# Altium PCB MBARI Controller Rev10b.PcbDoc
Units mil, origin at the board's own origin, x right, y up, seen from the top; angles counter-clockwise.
Board outline 10420.2 x 10420.2 mil, 2 copper layers (Top Layer, Bottom Layer); 250 components, 200 nets, 891 pads, 0 vias.
Unrouted connection lines stored in the file: 523.
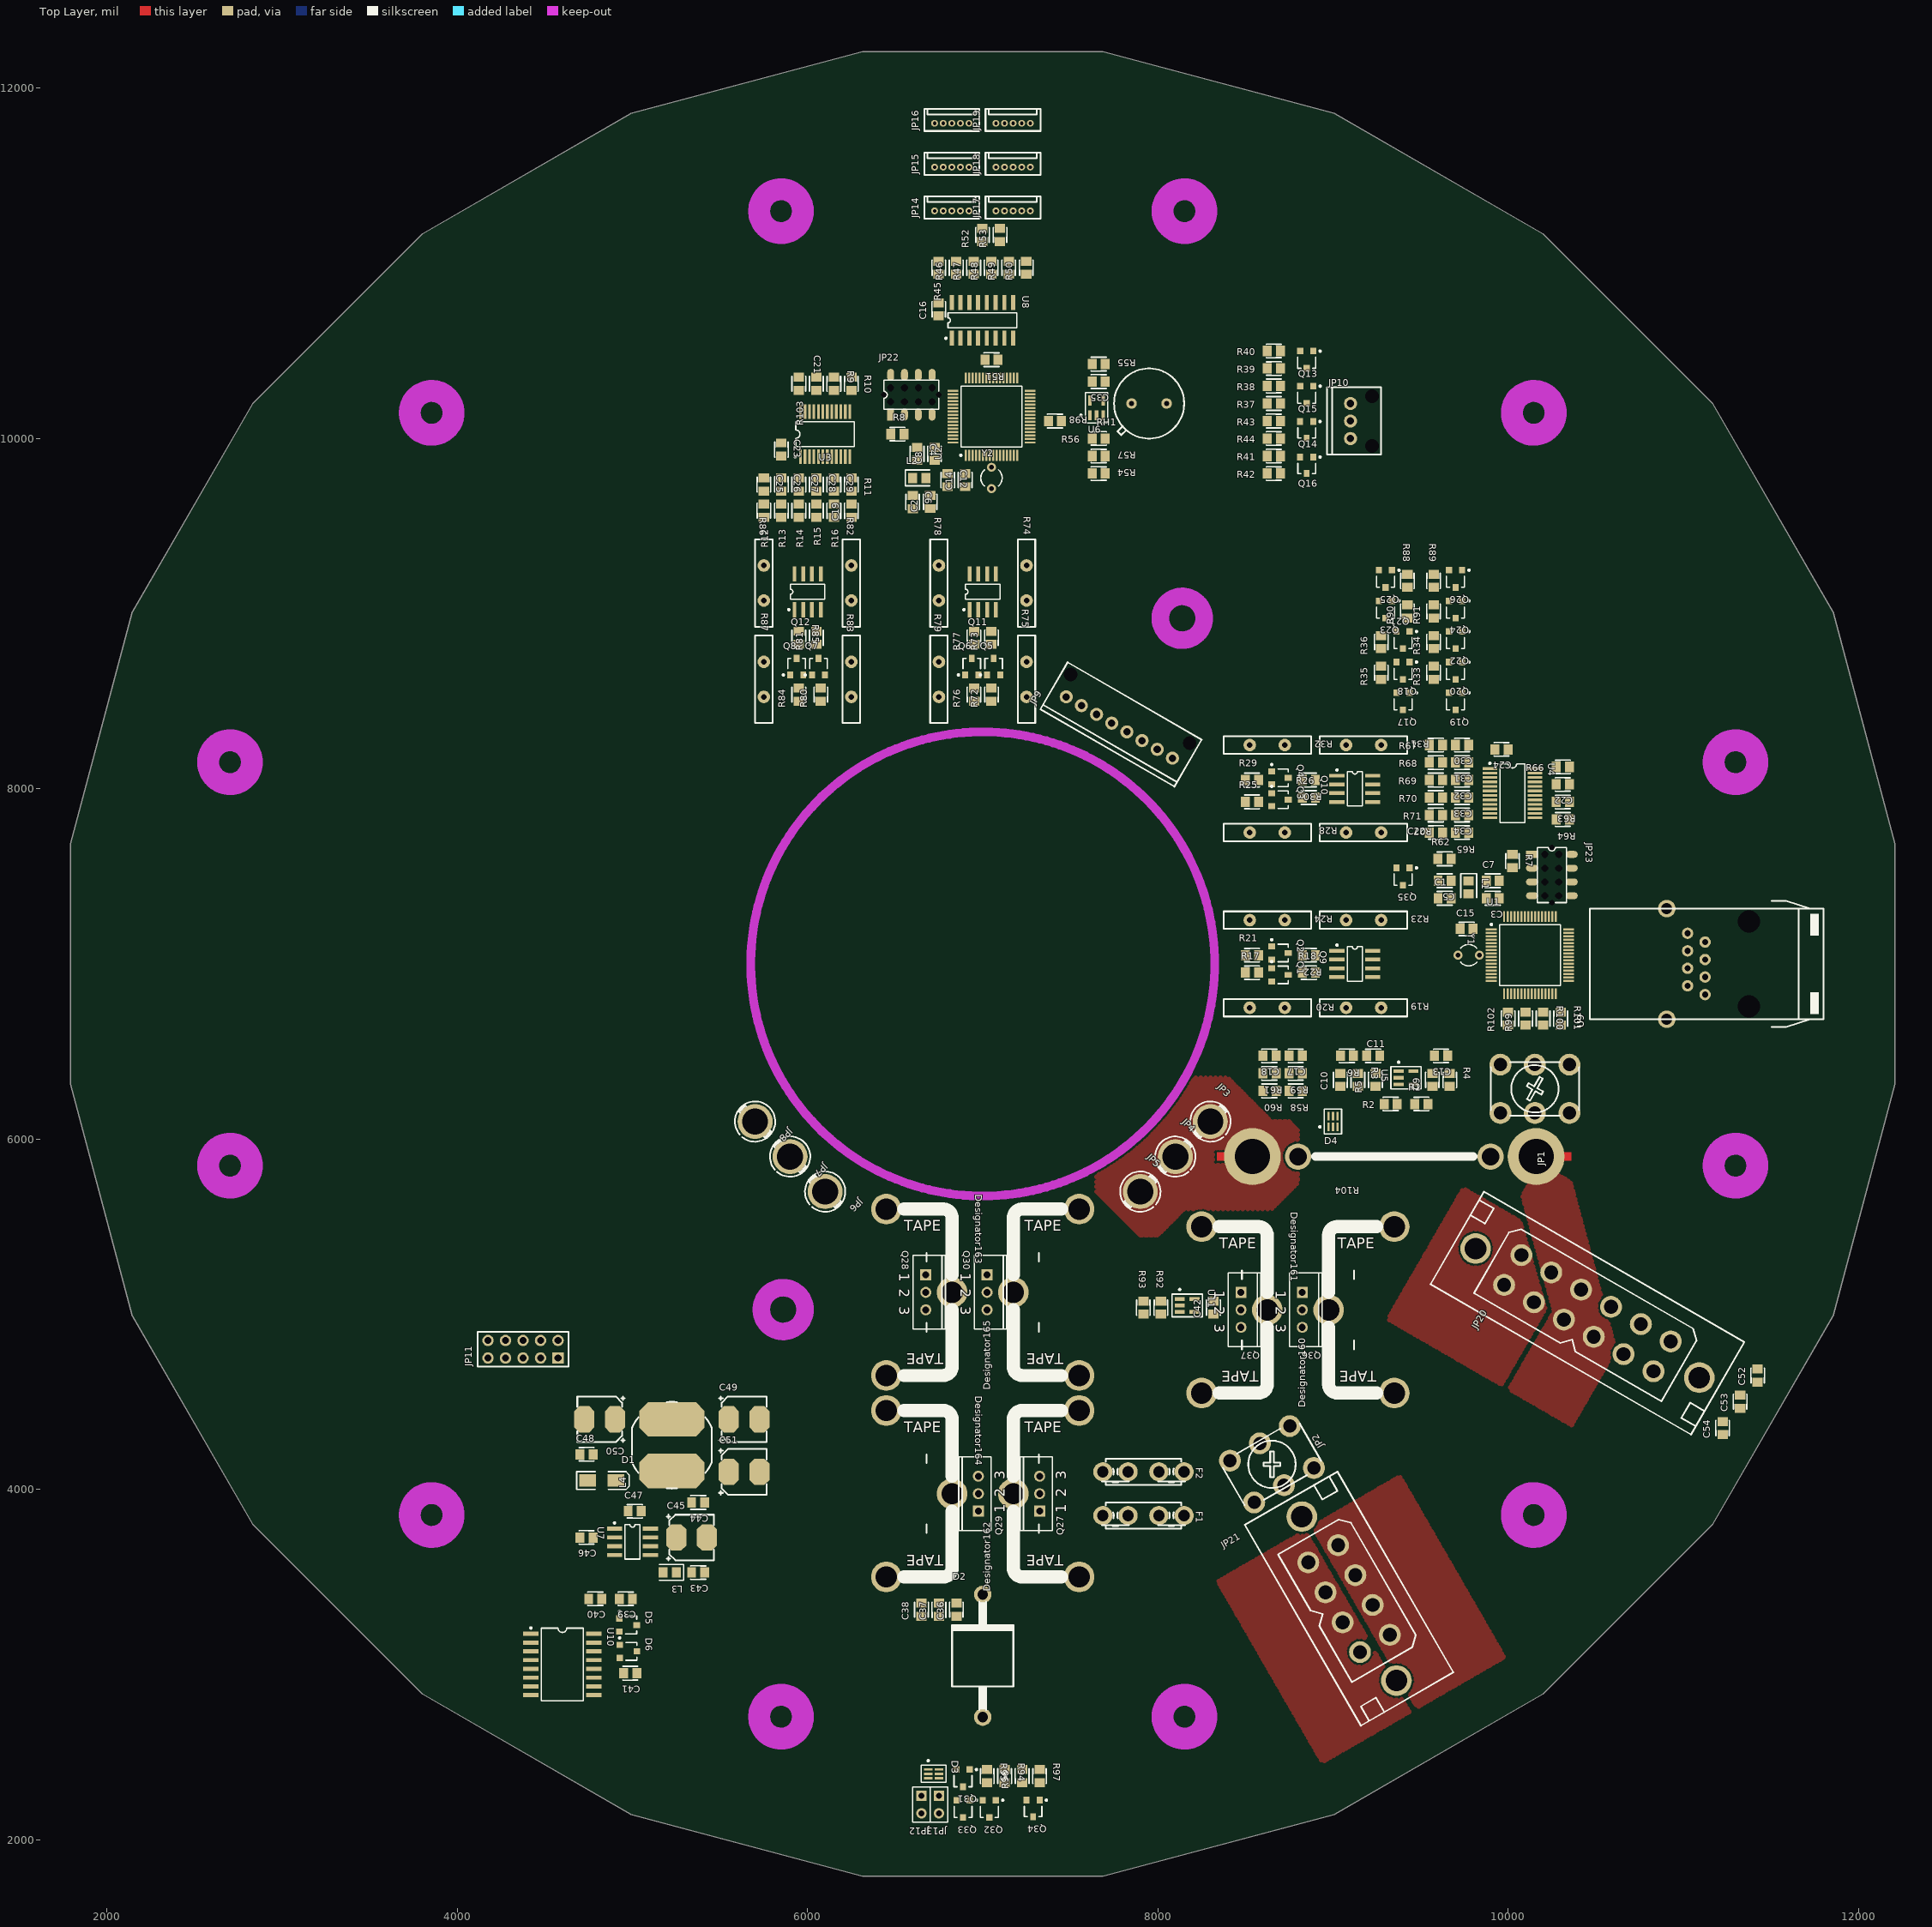
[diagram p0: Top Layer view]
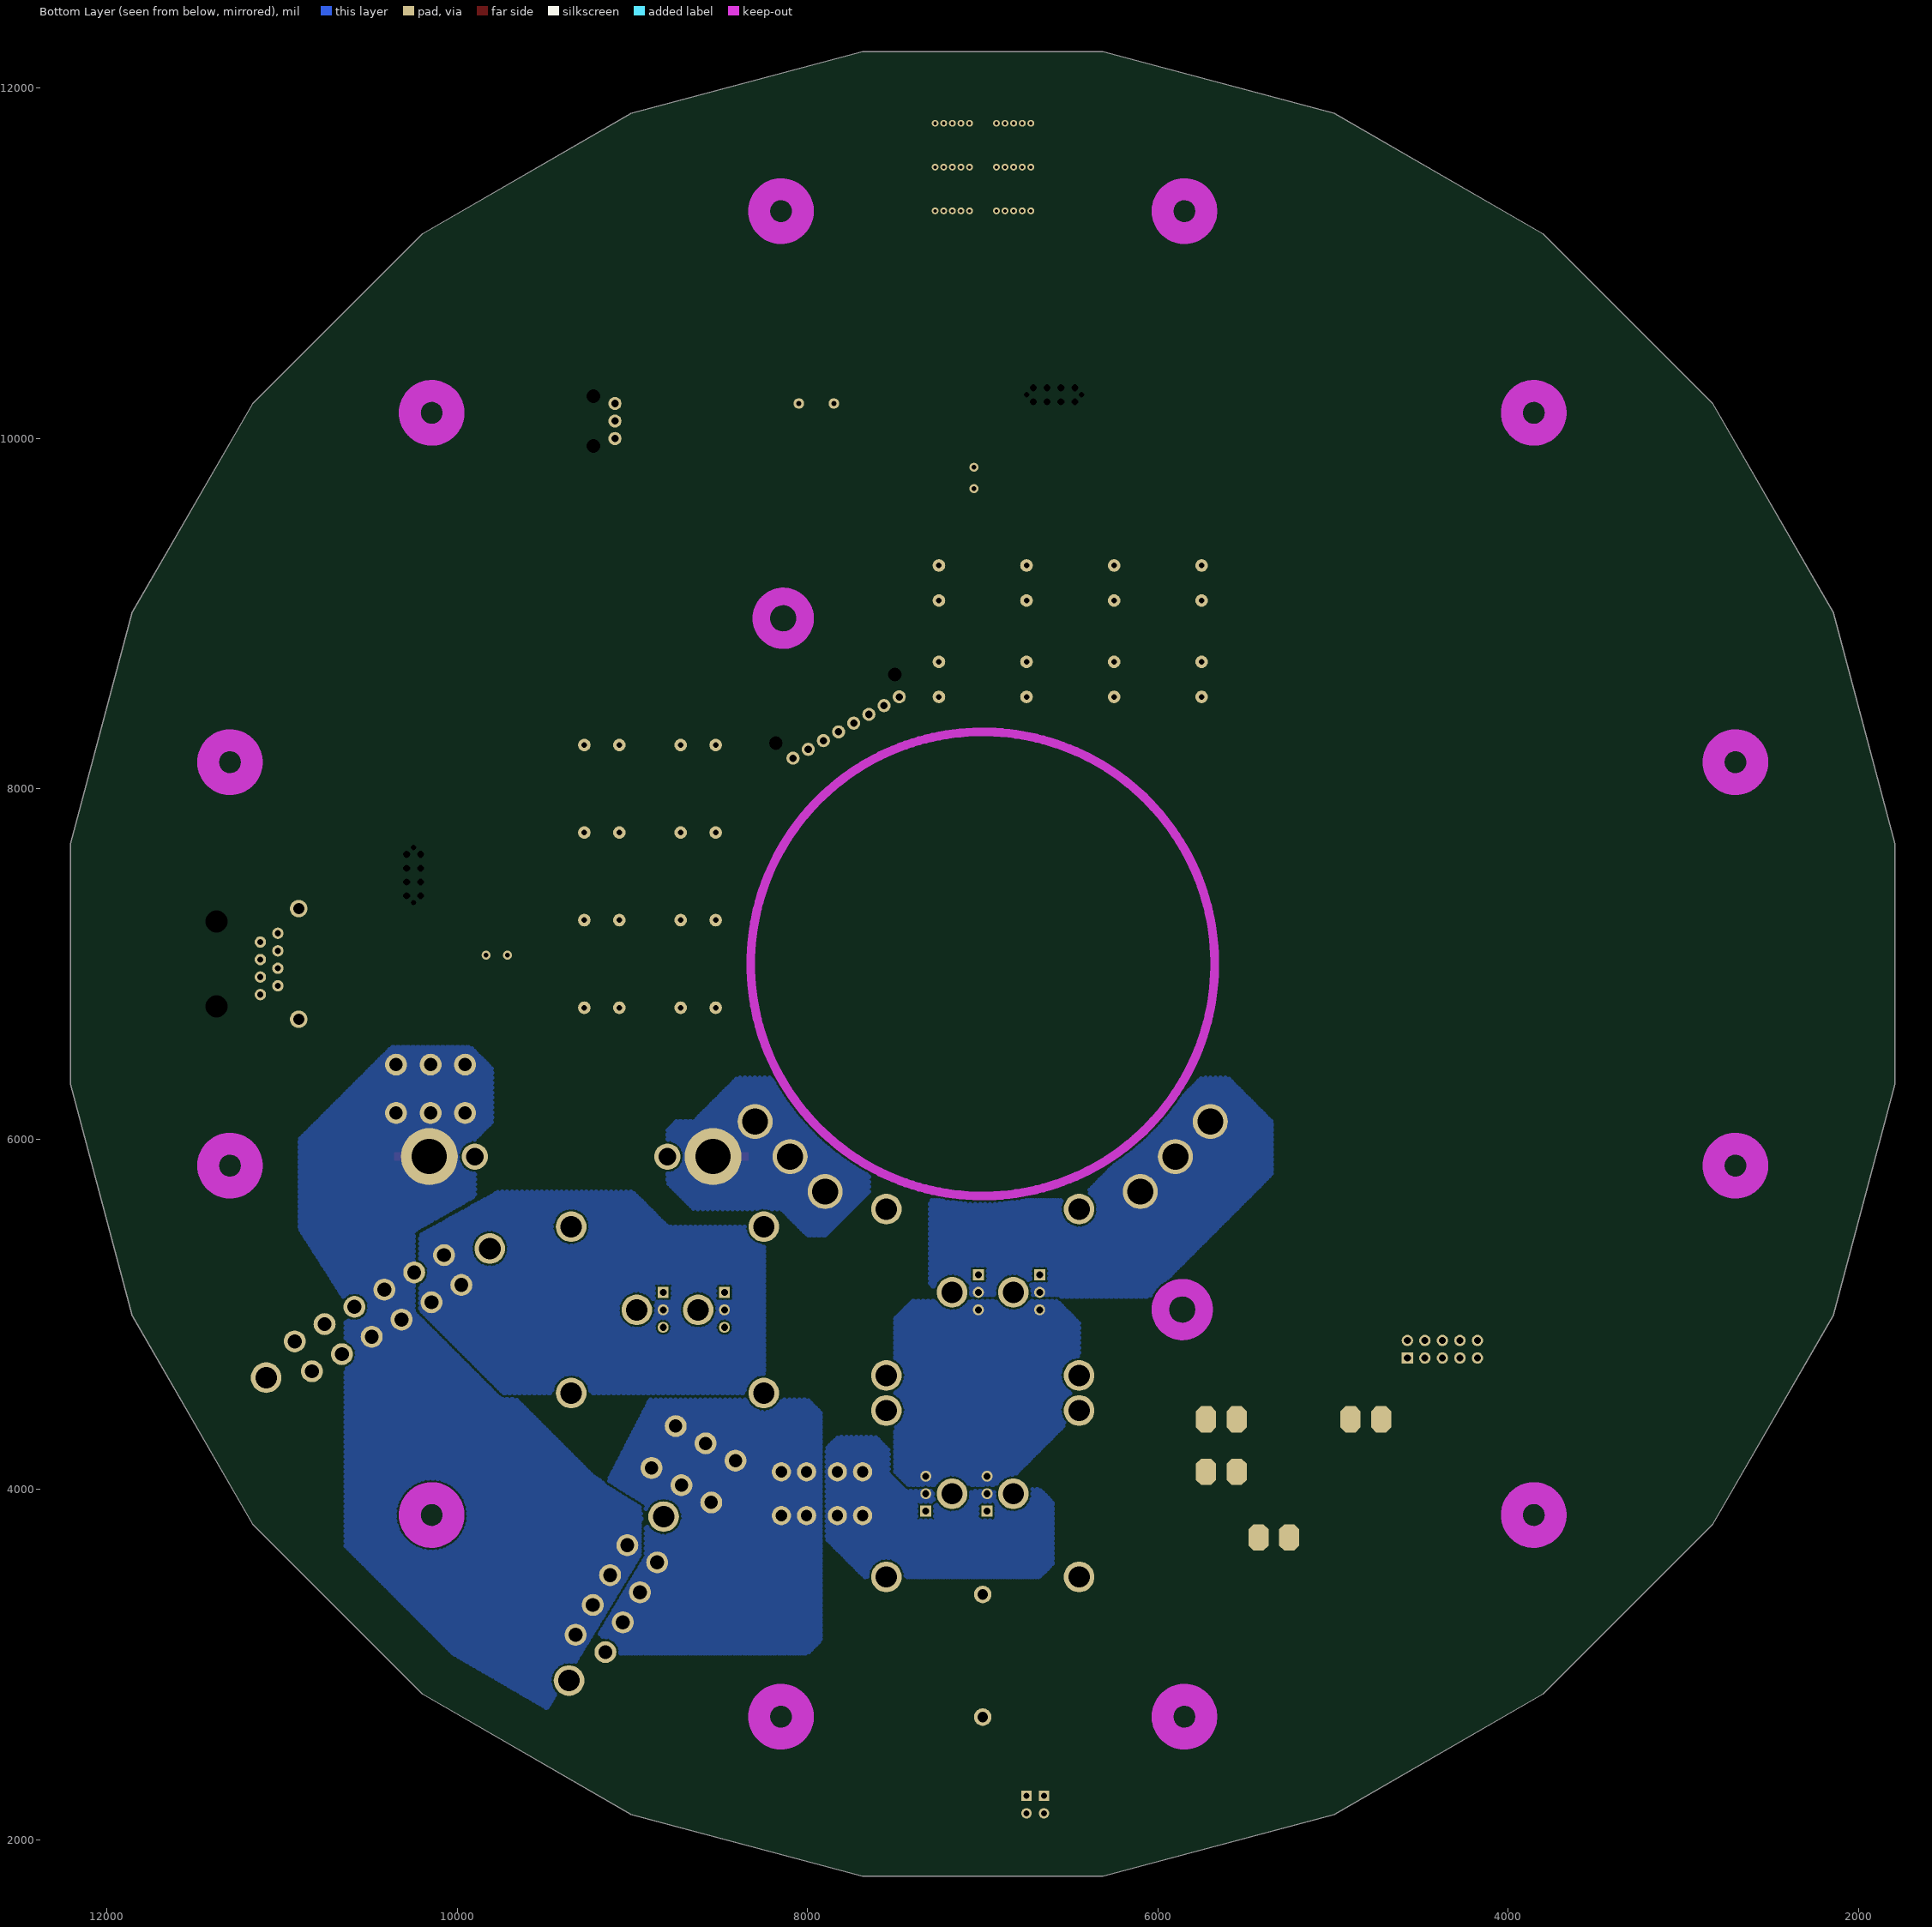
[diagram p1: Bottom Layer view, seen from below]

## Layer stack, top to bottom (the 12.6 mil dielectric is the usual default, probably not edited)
Top Layer: signal copper 1.4
Dielectric: dielectric 12.6, FR-4, Dk 4.8
Bottom Layer: signal copper 1.4

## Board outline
2145.29,4988.4 cw(c2149.63,4990.91) 2144.88,4989.33 cw(c2149.63,4990.91) 2144.79,4989.61 1790.07,6313.44 cw(c1794.91,6314.74) 1789.9,6314.74 ccw(c1794.91,6314.74) 1790.07,6313.44 1789.9,6314.74 1789.9,7685.26 cw(c1794.91,7685.26) 1790.08,7686.58 2144.79,9010.39 cw(c2149.63,9009.09) 2145.3,9011.62 2830.55,10198.5 cw(c2834.9,10196) 2831.35,10199.54 cw(c2834.9,10196) 2831.37,10199.56 2831.35,10199.54 3800.46,11168.65 cw(c3804,11165.1) 3801.52,11169.46 4988.4,11854.71 cw(c4990.91,11850.37) 4989.33,11855.12 cw(c4990.91,11850.37) 4989.61,11855.21 6313.44,12209.93 cw(c6314.74,12205.08) 6314.74,12210.1 ccw(c6314.74,12205.08) 6313.44,12209.93 6314.74,12210.1 7685.26,12210.1 cw(c7685.26,12205.08) 7686.58,12209.92 9010.39,11855.21 cw(c9009.09,11850.37) 9011.62,11854.7 10198.5,11169.45 cw(c10196,11165.1) 10199.54,11168.65 cw(c10196,11165.1) 10199.56,11168.63 10199.54,11168.65 11168.65,10199.54 cw(c11165.1,10196) 11169.46,10198.48 11854.71,9011.6 cw(c11850.37,9009.09) 11855.21,9010.37 11855.21,9010.39 ccw(c11850.37,9009.09) 11854.71,9011.6 11855.21,9010.37 12209.93,7686.56 cw(c12205.08,7685.26) 12210.1,7685.26 ccw(c12205.08,7685.26) 12209.93,7686.56 12210.1,7685.26 12210.1,6314.74 cw(c12205.08,6314.74) 12209.95,6313.52 cw(c12205.08,6314.74) 12209.93,6313.44 12209.93,6313.43 ccw(c12205.08,6314.74) 12209.93,6313.45 12209.93,6313.43 11855.21,4989.61 cw(c11850.37,4990.91) 11854.7,4988.38 11854.71,4988.4 ccw(c11850.37,4990.91) 11855.21,4989.61 11854.7,4988.38 11169.45,3801.5 cw(c11165.1,3804) 11168.65,3800.46 ccw(c11165.1,3804) 11169.45,3801.5 11168.65,3800.46 cw(c11165.1,3804) 11168.63,3800.44 11168.65,3800.46 10199.54,2831.35 cw(c10196,2834.9) 10198.48,2830.54 10198.5,2830.55 ccw(c10196,2834.9) 10199.54,2831.35 10198.48,2830.54 9011.6,2145.29 cw(c9009.09,2149.63) 9010.67,2144.88 ccw(c9009.09,2149.63) 9011.6,2145.29 9010.67,2144.88 cw(c9009.09,2149.63) 9010.39,2144.79 ccw(c9009.09,2149.63) 9010.67,2144.88 9010.39,2144.79 7686.56,1790.07 cw(c7685.26,1794.91) 7685.26,1789.9 ccw(c7685.26,1794.91) 7686.56,1790.07 7685.26,1789.9 6314.74,1789.9 cw(c6314.74,1794.91) 6313.42,1790.08 4989.61,2144.79 cw(c4990.91,2149.63) 4988.38,2145.3 3801.5,2830.55 cw(c3804,2834.9) 3800.46,2831.35 cw(c3804,2834.9) 3800.44,2831.37 3800.46,2831.35 2831.35,3800.46 cw(c2834.9,3804) 2830.54,3801.52

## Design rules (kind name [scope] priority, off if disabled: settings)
Clearance "Clearance - Polygon" [NOT(IsPolygon) vs (IsPolygon)] p1: gap=25
Clearance [NOT(IsPolygon) vs NOT(IsPolygon)] p2: gap=10
ComponentClearance [All] p1: gap=10 collisioncheckmode=0
PlaneClearance [All] p1: clearance=35
PolygonConnect [All] p1: connectstyle=Direct reliefconductorwidth=10 reliefentries=4 polygonreliefangle="90 Angle"
RoomDefinition "MBARI Controller Rev10b" [InComponentClass('MBARI Controller Rev10b')] p1: confinementstyle=ConfineIn formatcopy=TRUE outline 0,0 2000,0 2000,1000 0,1000
RoutingVias [All] p1: holewidth=10 width=25 viastyle="Through Hole" minholewidth=10 minwidth=25 maxholewidth=100 maxwidth=150
SolderMaskExpansion [All] p1: expansion=4
TestPointUsage [All] p1: valid=0 allowmultiple=FALSE
Testpoint [All] p1: side=15 testpointundercomponent=TRUE minsize=40 maxsize=100 preferedsize=60 minholesize=0 maxholesize=40 preferedholesize=32 testpointgrid=1 style=1023 order=-539222988
Width [All] p1: maxlimit=200 minlimit=10 preferedwidth=10
16 further rules are at their usual default settings.

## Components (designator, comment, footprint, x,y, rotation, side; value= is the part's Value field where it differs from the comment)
C1 "C0805" 0805 9637.6,7375 r0 top locked
C2 "C0805" 0805 6700,9637.6 r90 top locked
C3 "C0805" 0805 9912.4,7375 r180 top locked
C4 "C0805" 0805 6625,9912.4 r270 top locked
C5 "C0805" 0805 9637.6,7475 r180 top locked
C6 "C0805" 0805 6600,9637.4 r270 top locked
C7 "C0805" 0805 9912.6,7475 r0 top locked
C8 "C0805" 0805 6725,9912.4 r90 top locked
C9 "C0805" 0805 9567.32,6337.4 r90 top locked
C10 "C0805" 0805 9042.32,6337.4 r90 top locked
C11 "C0805" 0805 9229.72,6475 r0 top locked
C12 "C0805" 0805 6800,9762.4 r270 top locked
C13 "C0805" 0805 9617.32,6475 r180 top locked
C14 "C0805" 0805 6900,9762.4 r90 top locked
C15 "C0805" 0805 9762.6,7200 r0 top locked
C16 "C0805" 0805 6748.4,10737.4 r90 top locked
C17 "C0805" 0805 8787.4,6475 r180 top locked
C18 "C0805" 0805 8637.4,6475 r180 top locked
C19 "C0805" 0805 6250,9587.4 r90 top locked
C20 "C0805" 0805 9587.6,7750 r0 top locked
C21 "C0805" 0805 6050,10312.6 r270 top locked
C22 "C0805" 0805 10312.6,8025 r180 top locked
C23 "C0805" 0805 5850,9937.4 r270 top locked
C24 "C0805" 0805 9962.4,8225 r180 top locked
C25 "C0805" 0805 5750,9737.4 r270 top locked
C26 "C0805" 0805 5850,9737.8 r270 top locked
C27 "C0805" 0805 5950,9737.4 r270 top locked
C28 "C0805" 0805 6050,9737.6 r270 top locked
C29 "C0805" 0805 6150,9737.6 r270 top locked
C30 "C0805" 0805 9737.6,8250 r180 top locked
C31 "C0805" 0805 9737.6,8150 r180 top locked
C32 "C0805" 0805 9737.4,8050 r180 top locked
C33 "C0805" 0805 9737.4,7950 r180 top locked
C34 "C0805" 0805 9737.4,7850 r180 top locked
C35 "C0805" 0805 7662.4,10325 r180 top locked
C36 "C0805" 0805 6850,3312.4 r90 top locked
C37 "C0805" 0805 6750,3312.2 r90 top locked
C38 "C0805" 0805 6650,3312.4 r90 top locked
C39 "C0805" 0805 4962.4,3375 r180 top locked
C40 "C0805" 0805 4787.4,3375 r180 top locked
C41 "C0805" 0805 4987.6,2950 r180 top locked
C42 "C0805" 0805 8317.32,5037.4 r90 top locked
C43 "C0805" 0805 5375,3525 r180 top locked
C44 "C0805" 0805 5375,3925 r180 top locked
C45 "Cap Pol2" "CAP S/M 6.3DIA" 5250,3725 r0 top locked
C46 "C0805" 0805 4737.6,3725 r180 top locked
C47 "C0805" 0805 5012.6,3875 r0 top locked
C48 "C0805" 0805 4737.4,4200 r0 top locked
C49 "Cap Pol2" "CAP S/M 6.3DIA" 5550,4400 r0 top locked
C50 "Cap Pol2" "CAP S/M 6.3DIA" 4900,4400 r180 top locked
C51 "Cap Pol2" "CAP S/M 6.3DIA" 5550,4100 r0 top locked
C52 "C0805" 0805 11425,4650 r90 top locked
C53 "C0805" 0805 11325,4500 r90 top locked
C54 "C0805" 0805 11225,4350 r90 top locked
D1 "IR 10MQ060N" SMA 4825,4050 r0 top locked
D2 "D Zener" P600 7000,2700 r90 top locked
D3 "" SO-G6/Z2.8 6719.49,2375.59 r270 top locked
D4 "" SO-G6/Z2.8 9000,6100 r0 top locked
D5 "Diode BAS70" SO-G3/C2.5 4975,3225 r270 top locked
D6 "Diode BAS70" SO-G3/C2.5 4975.79,3075 r270 top locked
Designator160 "Comment" "TO220 576602" 9000,5025 r90 top locked
Designator161 "Comment" "TO220 576602" 8600,5025 r270 top locked
Designator162 "Comment" "TO220 576602" 7200,3975 r90 top locked
Designator163 "Comment" "TO220 576602" 6800,5125 r270 top locked
Designator164 "Comment" "TO220 576602" 6800,3975 r270 top locked
Designator165 "Comment" "TO220 576602" 7200,5125 r90 top locked
F1 "" "FUSECLIP MINI PCB" 7918,3850 r180 top locked
F2 "" "FUSECLIP MINI PCB" 7918,4100 r180 top locked
JP1 "Socket" "Terminal - screw" 9956,6149 r90 top locked
JP2 "Socket" "Terminal - screw" 8550,3925 r120 top locked
JP3 "TERMINAL 10AWG" "Terminal 10AWG crimp" 8300,6100 r315 top locked
JP4 "TERMINAL 10AWG" "Terminal 10AWG crimp" 8100,5900 r315 top locked
JP5 "TERMINAL 10AWG" "Terminal 10AWG crimp" 7900,5700 r315 top locked
JP6 "TERMINAL 10AWG" "Terminal 10AWG crimp" 6100,5700 r225 top locked
JP7 "TERMINAL 10AWG" "Terminal 10AWG crimp" 5900,5900 r225 top locked
JP8 "TERMINAL 10AWG" "Terminal 10AWG crimp" 5700,6100 r225 top locked
JP9 "Header 8 Shrouded" "MTA-100-8 SHROUDED" 7476.79,8525 r150 top locked
JP10 "Header 3 Shrouded" "MTA-100-3 Shrouded" 9100,10200 r90 top locked
JP11 "Header 5X2" "Header 5x2V" 4575,4750 r180 top locked (schematic designator JP22)
JP12 "Header 2" HDR1X2 6650,2250 r270 top locked
JP13 "Header 2" HDR1X2 6750,2250 r270 top locked
JP14 "HEADER 5X1" "Header 5x1.25mm Shrouded" 6921.8,11300 r180 top locked
JP15 "HEADER 5X1" "Header 5x1.25mm Shrouded" 6921.8,11550 r180 top locked
JP16 "HEADER 5X1" "Header 5x1.25mm Shrouded" 6921.8,11800 r180 top locked
JP17 "HEADER 5X1" "Header 5x1.25mm Shrouded" 7271.8,11300 r180 top locked
JP18 "HEADER 5X1" "Header 5x1.25mm Shrouded" 7271.8,11550 r180 top locked
JP19 "HEADER 5X1" "Header 5x1.25mm Shrouded" 7271.8,11800 r180 top locked
JP20 "Female" PLB12F3 10879.79,4760 r150 top locked
JP21 "Female" PLB08F3 9240,3120.21 r120 top locked
JP22 "HEADER 8F LOW" "Header 4x2 2mm fem low" 6474.41,10136.81 r0 top locked
JP23 "HEADER 8F LOW" "Header 4x2 2mm fem low" 10136.81,7625.59 r270 top locked
L1 "LQM21FN100N00L" CC2012-0805 9775,7437.4 r270 top locked
L2 "LQM21FN100N00L" CC2012-0805 6637.6,9775 r0 top locked
L3 "LQM21FN100N00L" CC2012-0805 5212.6,3525 r180 top locked
L4 "Inductor Iron" CDR125 5225,4105 r90 top locked
Q1 "BC847C" SOT23 8697.24,6937.6 r270 top locked
Q2 "BC847C" SOT23 8697.24,7062.4 r270 top locked
Q3 "BC847C" SOT23 8697.24,7937.6 r270 top locked
Q4 "BC847C" SOT23 8697.24,8062.6 r270 top locked
Q5 "BC847C" SOT23 7062.4,8697.24 r0 top locked
Q6 "BC847C" SOT23 6937.4,8697.24 r0 top locked
Q7 "BC847C" SOT23 6062.4,8697.24 r0 top locked
Q8 "BC847C" SOT23 5937.6,8697.24 r0 top locked
Q9 "IRF7328" SO-8 9125,7000 r270 top locked
Q10 "IRF7328" SO-8 9125,8000 r270 top locked
Q11 "IRF7328" SO-8 7000,9125 r0 top locked
Q12 "IRF7328" SO-8 6000,9125 r0 top locked
Q13 "BC856BLT1" 318-08 8850,10450 r180 top locked
Q14 "BC847C" SOT23 8850,10050 r180 top locked
Q15 "BC856BLT1" 318-08 8850,10250 r180 top locked
Q16 "BC847C" SOT23 8850,9847.24 r180 top locked
Q17 "BC856BLT1" 318-08 9400,8499.21 r180 top locked
Q18 "BC847CLT1" 318-08 9400,8674.21 r180 top locked
Q19 "BC856BLT1" 318-08 9700,8499.21 r180 top locked
Q20 "BC847CLT1" 318-08 9700,8674.21 r180 top locked
Q21 "BC856BLT1" 318-08 9400,8849.21 r180 top locked
Q22 "BC856BLT1" 318-08 9700,8849.21 r180 top locked
Q23 "BC847CLT1" 318-08 9300,9024.21 r180 top locked
Q24 "BC847CLT1" 318-08 9700,9024.21 r180 top locked
Q25 "BC847CLT1" 318-08 9300,9199.21 r180 top locked
Q26 "BC847CLT1" 318-08 9700,9199.21 r180 top locked
Q27 "IRF2804" TO-220AB 7325,3975 r90 top locked
Q28 "IRF2804" TO-220AB 6675,5125 r270 top locked
Q29 "IRF2804" TO-220AB 6975,3975 r90 top locked
Q30 "IRF2804" TO-220AB 7025,5125 r270 top locked
Q31 "BC847CLT1" 318-08 6887.4,2350.79 r180 top locked
Q32 "BC847CLT1" 318-08 7037.6,2175.79 r180 top locked
Q33 "BC847CLT1" 318-08 6887.6,2175.79 r180 top locked
Q34 "BSS84LT1" SOT23 7287.6,2177.76 r180 top locked
Q35 "BC847CLT1" 318-08 9400,7499.21 r180 top locked
Q36 "IRF2804" TO-220AB 8825,5025 r270 top locked
Q37 "IRF2804" TO-220AB 8475,5025 r270 top locked
R1 "ERJ6GE" C0805 9504.72,6200 r0 top locked
R2 "ERJ6GE" C0805 9329.92,6200 r180 top locked
R3 "ERJ6GE" C0805 9142.32,6337.4 r270 top locked
R4 "ERJ6GE" C0805 9667.32,6337.6 r270 top locked
R5 "ERJ6GE" C0805 9242.32,6337.4 r90 top locked
R6 "ERJ6GE" C0805 9079.72,6475 r180 top locked
R7 "ERJ6GE" C0805 10025,7587.4 r270 top locked
R8 "ERJ6GE" C0805 6512.6,10025 r0 top locked
R9 "ERJ6GE" C0805 6150,10312.4 r270 top locked
R10 "ERJ6GE" C0805 6250,10312.6 r270 top locked
R11 "ERJ6GE" C0805 6250,9737.4 r270 top locked
R12 "ERJ6GE" C0805 5750,9587.6 r90 top locked
R13 "ERJ6GE" C0805 5850,9587.8 r90 top locked
R14 "ERJ6GE" C0805 5950,9587.6 r90 top locked
R15 "ERJ6GE" C0805 6050,9587.6 r90 top locked
R16 "ERJ6GE" C0805 6150,9587.4 r90 top locked
R17 "ERJ6GE" C0805 8537.4,6950 r0 top locked
R18 "ERJ6GE" C0805 8862.6,6950 r0 top locked
R19 "" "Resistor 5W - ceramic" 9275,6750 r180 top locked
R20 "" "Resistor 5W - ceramic" 8725,6750 r180 top locked
R21 "ERJ6GE" C0805 8537.6,7050 r0 top locked
R22 "ERJ6GE" C0805 8862.6,7050 r180 top locked
R23 "" "Resistor 5W - ceramic" 9275,7250 r180 top locked
R24 "" "Resistor 5W - ceramic" 8725,7250 r180 top locked
R25 "ERJ6GE" C0805 8537.4,7925.2 r0 top locked
R26 "ERJ6GE" C0805 8862.6,7950 r0 top locked
R27 "" "Resistor 5W - ceramic" 9275,7750 r180 top locked
R28 "" "Resistor 5W - ceramic" 8725,7750 r180 top locked
R29 "ERJ6GE" C0805 8537.4,8050.2 r0 top locked
R30 "ERJ6GE" C0805 8862.6,8050 r180 top locked
R31 "" "Resistor 5W - ceramic" 9275,8250 r180 top locked
R32 "" "Resistor 5W - ceramic" 8725,8250 r180 top locked
R33 "ERJ6GE" C0805 9575,8662.4 r90 top locked
R34 "ERJ6GE" C0805 9575,8837.4 r90 top locked
R35 "ERJ6GE" C0805 9275,8662.4 r90 top locked
R36 "ERJ6GE" C0805 9275,8837.4 r90 top locked
R37 "ERJ6GE" C0805 8662.4,10200 r0 top locked
R38 "ERJ6GE" C0805 8662.6,10300 r180 top locked
R39 "ERJ6GE" C0805 8662.4,10400 r0 top locked
R40 "ERJ6GE" C0805 8662.4,10500 r180 top locked
R41 "ERJ6GE" C0805 8662.6,9900 r180 top locked
R42 "ERJ6GE" C0805 8662.4,9800 r180 top locked
R43 "ERJ6GE" C0805 8662.4,10100 r180 top locked
R44 "ERJ6GE" C0805 8662.6,10000 r180 top locked
R45 "ERJ6GE" C0805 6748.4,10975 r90 top locked
R46 "ERJ6GE" C0805 6848.4,10975 r90 top locked
R47 "ERJ6GE" C0805 6948.4,10975 r90 top locked
R48 "ERJ6GE" C0805 7048.4,10975 r90 top locked
R49 "ERJ6GE" C0805 7148.4,10975 r90 top locked
R50 "ERJ6GE" C0805 7248.4,10975 r90 top locked
R51 "ERJ6GE" C0805 7050,10450 r180 top locked
R52 "ERJ6GE" C0805 6998.4,11162.6 r90 top locked
R53 "ERJ6GE" C0805 7098.4,11162.6 r90 top locked
R54 "ERJ6GE" C0805 7662.4,9800 r180 top locked
R55 "ERJ6GE" C0805 7662.4,10425 r180 top locked
R56 "ERJ6GE" C0805 7662.6,10000 r0 top locked
R57 "ERJ6GE" C0805 7662.6,9900 r180 top locked
R58 "ERJ6GE" C0805 8787.2,6275 r180 top locked
R59 "ERJ6GE" C0805 8787.2,6375 r180 top locked
R60 "ERJ6GE" C0805 8637.4,6275 r180 top locked
R61 "ERJ6GE" C0805 8637.4,6375 r180 top locked
R62 "ERJ6GE" C0805 9637.4,7600 r0 top locked
R63 "ERJ6GE" C0805 10312.4,7925 r180 top locked
R64 "ERJ6GE" C0805 10312.4,7825 r180 top locked
R65 "ERJ6GE" C0805 9737.6,7750 r180 top locked
R66 "ERJ6GE" C0805 10312.6,8125 r0 top locked
R67 "ERJ6GE" C0805 9587.4,8250 r0 top locked
R68 "ERJ6GE" C0805 9587.4,8150 r0 top locked
R69 "ERJ6GE" C0805 9587.4,8050 r0 top locked
R70 "ERJ6GE" C0805 9587.4,7950 r0 top locked
R71 "ERJ6GE" C0805 9587.4,7850 r0 top locked
R72 "ERJ6GE" C0805 7050,8537.4 r90 top locked
R73 "ERJ6GE" C0805 7050,8862.4 r90 top locked
R74 "" "Resistor 5W - ceramic" 7250,9275 r270 top locked
R75 "" "Resistor 5W - ceramic" 7250,8725 r270 top locked
R76 "ERJ6GE" C0805 6950,8537.4 r90 top locked
R77 "ERJ6GE" C0805 6950,8862.4 r90 top locked
R78 "" "Resistor 5W - ceramic" 6750,9275 r270 top locked
R79 "" "Resistor 5W - ceramic" 6750,8725 r270 top locked
R80 "ERJ6GE" C0805 6075,8537.6 r90 top locked
R81 "ERJ6GE" C0805 6050,8862.4 r90 top locked
R82 "" "Resistor 5W - ceramic" 6250,9275 r270 top locked
R83 "" "Resistor 5W - ceramic" 6250,8725 r270 top locked
R84 "ERJ6GE" C0805 5950,8537.6 r90 top locked
R85 "ERJ6GE" C0805 5950,8862.6 r270 top locked
R86 "" "Resistor 5W - ceramic" 5750,9275 r270 top locked
R87 "" "Resistor 5W - ceramic" 5750,8725 r270 top locked
R88 "ERJ6GE" C0805 9425,9187.4 r270 top locked
R89 "ERJ6GE" C0805 9575,9187.4 r270 top locked
R90 "ERJ6GE" C0805 9425,9012.4 r90 top locked
R91 "ERJ6GE" C0805 9575,9012.4 r90 top locked
R92 "ERJ6GE" C0805 8017.32,5037.4 r270 top locked
R93 "ERJ6GE" C0805 7917.32,5037.6 r270 top locked
R94 "ERJ6GE" C0805 7125,2362.4 r270 top locked
R95 "ERJ6GE" C0805 7025,2362.4 r270 top locked
R96 "ERJ6GE" C0805 7225,2362.4 r90 top locked
R97 "ERJ6GE" C0805 7325,2362.4 r270 top locked
R98 "ERJ6GE" C0805 7412.4,10100 r180 top locked
R99 "ERJ6GE" C0805 10100,6687.6 r90 top locked
R100 "ERJ6GE" C0805 10200,6687.6 r270 top locked
R101 "ERJ6GE" C0805 10300,6687.6 r270 top locked
R102 "ERJ6GE" C0805 10000,6687.6 r90 top locked
R103 "ERJ6GE" C0805 5950,10312.6 r90 top locked
R104 "Resistor Shunt 4-term" "Shunt PCB-BH-50-50" 9350,5900 r180 top locked
RH1 "HS1101" HS1101 7850,10200 r0 top locked
U1 "" F-QFP10x10-G64/N 10125,7050 r0 top locked
U2 "" F-QFP10X10-G64/N 7050,10125 r90 top locked
U3 "BQ29312" SSO-G24/P.65 6100,10025 r0 top locked
U4 "BQ29312" SSO-G24/P.65 10025,7975 r270 top locked
U5 "LM7131ACM5" MA05A 9417.32,6350 r270 top locked
U6 "LM7131ACM5" MA05A 7650,10175 r0 top locked
U7 "Max5033" SO-G8 5000,3700 r270 top locked
U8 "MC74VHC138D" 751B-05 6998.4,10675 r0 top locked
U9 "XPort" XPort 11025,7175 r180 top locked
U10 "TC962COE" SO-G16/G6.9 4600,3000 r270 top locked
U11 "MAX9075EUK-T" SOT23-5 8167.32,5050 r270 top locked
Y1 "32kHz" BCY-W2/D3.1 9775,7050 r270 top locked
Y2 "32kHz" BCY-W2/D3.1 7050,9775 r0 top locked

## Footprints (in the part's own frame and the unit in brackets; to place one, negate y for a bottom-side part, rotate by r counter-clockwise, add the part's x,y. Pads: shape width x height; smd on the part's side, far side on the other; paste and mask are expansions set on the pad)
318-08 [mm] "SOT-23; 3 Leads; Body 3.0 x 2.6 mm, inc. leads (LxW max)"
  rect 0.9x0.95 smd: 1(-0.95,-1.25) 2(0.95,-1.25) 3(0,1.25)
  silkscreen extent -2.08,-1.37 1.3,1.25
751B-05 [mm] "Small Outline; 16 Leads; Body Width 3.9 mm; Pitch 1.27 mm"
  rect 0.6x2.2 smd: 1(-4.445,-2.6) 2(-3.175,-2.6) 3(-1.905,-2.6) 4(-0.635,-2.6) 5(0.635,-2.6) 6(1.905,-2.6) 7(3.175,-2.6) 8(4.445,-2.6) 9(4.445,2.6) 10(3.175,2.6) 11(1.905,2.6) 12(0.635,2.6) 13(-0.635,2.6) 14(-1.905,2.6) 15(-3.175,2.6) 16(-4.445,2.6)
  silkscreen extent -5.42,-2.72 5,1.1
0805 [mm] "Chip Capacitor; Body 2.0 x 1.2 mm (LxW typ)"
  rect 1.3x1.5 smd: 1(-0.95,0) 2(0.95,0)
  silkscreen extent -1.1,-1 1.1,1
BCY-W2/D3.1 [mm]
  round 1.3 hole 0.7: 1(0,1.55) 2(0,-1.55)
  silkscreen extent -1.55,-1.19 1.55,1.17
C0805 [mm] "Chip Capacitor; Body 2.0 x 1.2 mm (LxW typ)"
  rect 1.3x1.5 smd: 1(-0.95,0) 2(0.95,0)
  silkscreen extent -1.1,-1 1.1,1
"CAP S/M 6.3DIA" [mil] "Panasonic EEV; Nichicon UUD"
  oct 115x150 all layers, no hole: 1(0,0) 2(175,0)
  silkscreen extent -55,-130 215,130
CC2012-0805 [mm]
  rect 1.3x1.5 smd: 1(-0.95,0) 2(0.95,0)
  silkscreen extent -2,-1.15 1.5,1.15
CDR125 [mil] "Sumida inductor"
  oct 197x374 smd: 1(0,0) 2(295,0)
  silkscreen extent -100,-228 396,228
F-QFP10x10-G64/N [mm]
  rect 1.6x0.3 smd: 1(-5.6,3.75) 2(-5.6,3.25) 3(-5.6,2.75) 4(-5.6,2.25) 5(-5.6,1.75) 6(-5.6,1.25) 7(-5.6,0.75) 8(-5.6,0.25) 9(-5.6,-0.25) 10(-5.6,-0.75) 11(-5.6,-1.25) 12(-5.6,-1.75) 13(-5.6,-2.25) 14(-5.6,-2.75) 15(-5.6,-3.25) 16(-5.6,-3.75) 33(5.6,-3.75) 34(5.6,-3.25) 35(5.6,-2.75) 36(5.6,-2.25) 37(5.6,-1.75) 38(5.6,-1.25) 39(5.6,-0.75) 40(5.6,-0.25) 41(5.6,0.25) 42(5.6,0.75) 43(5.6,1.25) 44(5.6,1.75) 45(5.6,2.25) 46(5.6,2.75) 47(5.6,3.25) 48(5.6,3.75)
  rect 0.3x1.6 smd: 17(-3.75,-5.6) 18(-3.25,-5.6) 19(-2.75,-5.6) 20(-2.25,-5.6) 21(-1.75,-5.6) 22(-1.25,-5.6) 23(-0.75,-5.6) 24(-0.25,-5.6) 25(0.25,-5.6) 26(0.75,-5.6) 27(1.25,-5.6) 28(1.75,-5.6) 29(2.25,-5.6) 30(2.75,-5.6) 31(3.25,-5.6) 32(3.75,-5.6) 49(3.75,5.6) 50(3.25,5.6) 51(2.75,5.6) 52(2.25,5.6) 53(1.75,5.6) 54(1.25,5.6) 55(0.75,5.6) 56(0.25,5.6) 57(-0.25,5.6) 58(-0.75,5.6) 59(-1.25,5.6) 60(-1.75,5.6) 61(-2.25,5.6) 62(-2.75,5.6) 63(-3.25,5.6) 64(-3.75,5.6)
  silkscreen extent -5.72,-4.4 4.4,4.57
F-QFP10X10-G64/N [mm]
  rect 1.6x0.3 smd: 1(-5.6,3.75) 2(-5.6,3.25) 3(-5.6,2.75) 4(-5.6,2.25) 5(-5.6,1.75) 6(-5.6,1.25) 7(-5.6,0.75) 8(-5.6,0.25) 9(-5.6,-0.25) 10(-5.6,-0.75) 11(-5.6,-1.25) 12(-5.6,-1.75) 13(-5.6,-2.25) 14(-5.6,-2.75) 15(-5.6,-3.25) 16(-5.6,-3.75) 33(5.6,-3.75) 34(5.6,-3.25) 35(5.6,-2.75) 36(5.6,-2.25) 37(5.6,-1.75) 38(5.6,-1.25) 39(5.6,-0.75) 40(5.6,-0.25) 41(5.6,0.25) 42(5.6,0.75) 43(5.6,1.25) 44(5.6,1.75) 45(5.6,2.25) 46(5.6,2.75) 47(5.6,3.25) 48(5.6,3.75)
  rect 0.3x1.6 smd: 17(-3.75,-5.6) 18(-3.25,-5.6) 19(-2.75,-5.6) 20(-2.25,-5.6) 21(-1.75,-5.6) 22(-1.25,-5.6) 23(-0.75,-5.6) 24(-0.25,-5.6) 25(0.25,-5.6) 26(0.75,-5.6) 27(1.25,-5.6) 28(1.75,-5.6) 29(2.25,-5.6) 30(2.75,-5.6) 31(3.25,-5.6) 32(3.75,-5.6) 49(3.75,5.6) 50(3.25,5.6) 51(2.75,5.6) 52(2.25,5.6) 53(1.75,5.6) 54(1.25,5.6) 55(0.75,5.6) 56(0.25,5.6) 57(-0.25,5.6) 58(-0.75,5.6) 59(-1.25,5.6) 60(-1.75,5.6) 61(-2.25,5.6) 62(-2.75,5.6) 63(-3.25,5.6) 64(-3.75,5.6)
  silkscreen extent -5.72,-4.4 4.4,4.57
"FUSECLIP MINI PCB" [mil] "Keystone #3544 x2"
  round 110 hole 65: 1(-232,0) 1(-88,0) 2(88,0) 2(232,0)
  silkscreen extent -238,-75 238,75
HDR1X2 [mm] "Connector; Header; 2 Position"
  rect 1.5x1.5 hole 0.9: 1(0,0)
  round 1.5 hole 0.9: 2(2.54,0)
  silkscreen extent -1.27,-1.27 3.81,1.27
"Header 4x2 2mm fem low" [mm] "Molex 87340-0822"
  round 0 hole 0.8: 0(-1,2.875) 0(7,2.875)
  round 0 hole 1 unplated: 0(0,1.875) 0(0,3.875) 0(2,1.875) 0(2,3.875) 0(4,1.875) 0(4,3.875) 0(6,1.875) 0(6,3.875)
  rect 1x1.75 smd: 1(0,0)
  oval 1x1.75 smd: 2(2,0) 3(4,0) 4(6,0) 5(6,5.75) 6(4,5.75) 7(2,5.75) 8(0,5.75)
  silkscreen extent -1,0.78 7,4.97
"Header 5x1.25mm Shrouded" [mil] "Molex 53047"
  round 39 hole 20: 1(0,0) 2(49.2,0) 3(98.4,0) 4(147.6,0) 5(196.8,0)
  silkscreen extent -59,-82 256,44
"Header 5x2V" [mil] "Sullins PPTC052LFBN etc."
  rect 65x65 hole 40: 1(0,0)
  round 65 hole 40: 2(0,-100) 3(100,0) 4(100,-100) 5(200,0) 6(200,-100) 7(300,0) 8(300,-100) 9(400,0) 10(400,-100)
  silkscreen extent -60,-150 460,50
HS1101 [mil] "Humirel sensor"
  round 60 hole 30: 1(0,0) 2(200,0)
  silkscreen extent -100,-200 300,200
MA05A [mm] "SOT-23/SC-74A; 5 Leads; Body 3 x 3 mm, inc. leads (LxW max)"
  rect 0.5x1.45 smd: 1(-0.95,-1.075) 2(0,-1.075) 3(0.95,-1.075) 4(0.95,1.075) 5(-0.95,1.075)
  silkscreen extent -2.37,-2.2 1.6,2.2
"MTA-100-3 Shrouded" [mil] "AMP MTA-100"
  round 0 hole 78 unplated: 0(-242,-124) 0(42,-124)
  round 75 hole 42: 1(0,0) 2(-100,0) 3(-200,0)
  silkscreen extent -292,-175 92,135
"MTA-100-8 SHROUDED" [mil] "AMP MTA-100"
  round 0 hole 78 unplated: 0(-742,-124) 0(42,-124)
  round 75 hole 42: 1(0,0) 2(-100,0) 3(-200,0) 4(-300,0) 5(-400,0) 6(-500,0) 7(-600,0) 8(-700,0)
  silkscreen extent -792,-175 92,135
P600 [mil] "Axial .35x.35-.052"
  round 100 hole 60: 1(0,0) 2(700,0)
  silkscreen extent 40,-175 660,175
PLB08F3 [mil] "Positronic PLB08 fem vert"
  round 175 hole 123: 0(-245,0) 0(836,0)
  round 125 hole 80: 1(591,99) 2(394,99) 3(197,100) 4(0,99) 5(591,-98) 6(394,-98) 7(197,-98) 8(0,-98)
  silkscreen extent -367,-305 958,305
PLB12F3 [mil] "Positronic PLB12 fem vert"
  round 175 hole 123: 0(-245,0) 0(1230,0)
  round 125 hole 80: 1(985,99) 2(788,99) 3(591,99) 4(394,99) 5(197,100) 6(0,99) 7(985,-98) 8(788,-98) 9(591,-98) 10(394,-98) 11(197,-98) 12(0,-98)
  silkscreen extent -366,-305 1351,305
"Resistor 5W - ceramic" [mil]
  round 72 hole 32: 1(0,0) 2(200,0)
  silkscreen extent -150,-50 350,50
"Shunt PCB-BH-50-50" [mil] "Canadian Shunt"
  round 325 hole 200: 1(-810,0) 4(810,0)
  round 150 hole 100: 2(-550,0) 3(550,0)
  Top Layer region: -1012.5,-25 -950,-25 -950,25 -1012.5,25
  Top Layer region: 1012.5,25 950,25 950,-25 1012.5,-25
  silkscreen extent -450,0 450,0
SMA [mm] "DO-214-AC/SMA; 2 C-Bend Leads; Body 5 x 2.7 mm, inc. leads (LxW)"
  rect 2.4x1.8 smd: 1(-2.05,0) 2(2.05,0)
  silkscreen extent -3.65,-1.3 3.95,1.3
SO-8 [mm] "Plastic Small Outline; 8 Leads; Body Width 3.9 mm"
  rect 0.55x2.2 smd: 1(-1.905,-2.6) 2(-0.635,-2.6) 3(0.635,-2.6) 4(1.905,-2.6) 5(1.905,2.6) 6(0.635,2.6) 7(-0.635,2.6) 8(-1.905,2.6)
  silkscreen extent -2.85,-2.72 2.5,1.1
SO-G3/C2.5 [mm]
  rect 0.9x0.95 smd: 1(-0.95,-1.25) 2(0.95,-1.25) 3(0,1.25)
  silkscreen extent -2.07,-1.37 1.3,1.25
SO-G6/Z2.8 [mm]
  rect 0.35x1.25 smd: 1(-0.65,-0.775) 2(0,-0.775) 3(0.65,-0.775) 4(0.65,0.775) 5(0,0.775) 6(-0.65,0.775)
  silkscreen extent -2.02,-1.8 1.25,1.8
SO-G8 [mm]
  rect 0.6x2.2 smd: 1(-1.905,-2.6) 2(-0.635,-2.6) 3(0.635,-2.6) 4(1.905,-2.6) 5(1.905,2.6) 6(0.635,2.6) 7(-0.635,2.6) 8(-1.905,2.6)
  silkscreen extent -2.88,-2.72 2.5,1.1
SO-G16/G6.9 [mm]
  rect 0.6x2.25 smd: 1(-4.445,-4.575) 2(-3.175,-4.575) 3(-1.905,-4.575) 4(-0.635,-4.575) 5(0.635,-4.575) 6(1.905,-4.575) 7(3.175,-4.575) 8(4.445,-4.575) 9(4.445,4.575) 10(3.175,4.575) 11(1.905,4.575) 12(0.635,4.575) 13(-0.635,4.575) 14(-1.905,4.575) 15(-3.175,4.575) 16(-4.445,4.575)
  silkscreen extent -5.42,-4.7 5.27,3.05
SOT23 [mm] "SOT-23; 3 Leads; Body 3.0 x 2.5 mm, inc. leads (LxW max)"
  rect 0.85x1 smd: 1(-0.95,-1.2) 2(0.95,-1.2) 3(0,1.2)
  silkscreen extent -2.05,-1.32 1.28,1.2
SOT23-5 [mm] "SOT-23/SC-74A; 5 Leads; Body 3 x 3 mm, inc. leads (LxW max)"
  rect 0.55x1.45 smd: 1(-0.95,-1.075) 2(0,-1.075) 3(0.95,-1.075) 4(0.95,1.075) 5(-0.95,1.075)
  silkscreen extent -2.42,-2.2 1.65,2.2
SSO-G24/P.65 [mm]
  rect 0.4x2.15 smd: 1(-3.575,-3.275) 2(-2.925,-3.275) 3(-2.275,-3.275) 4(-1.625,-3.275) 5(-0.975,-3.275) 6(-0.325,-3.275) 7(0.325,-3.275) 8(0.975,-3.275) 9(1.625,-3.275) 10(2.275,-3.275) 11(2.925,-3.275) 12(3.575,-3.275) 13(3.575,3.275) 14(2.925,3.275) 15(2.275,3.275) 16(1.625,3.275) 17(0.975,3.275) 18(0.325,3.275) 19(-0.325,3.275) 20(-0.975,3.275) 21(-1.625,3.275) 22(-2.275,3.275) 23(-2.925,3.275) 24(-3.575,3.275)
  silkscreen extent -4.45,-3.4 4.25,1.8
"Terminal 10AWG crimp" [mil] "AMP 794037-1 wire to pcb"
  round 200 hole 148: 1(0,0)
  silkscreen extent -115,-115 115,115
"Terminal - screw" [mil] "Keystone #8199"
  round 125 hole 76: 1(0,0) 1(0,-197) 1(0,-394) 1(276,-394) 1(276,-197) 1(276,0)
  silkscreen extent -15,-450 291,55
"TO220 576602" [mil] "Aavid 576602T00000"
  round 175 hole 122: 0(-475,-350) 0(0,25) 0(475,-350)
  silkscreen extent -475,-250 475,25
TO-220AB [mm] "TO, Thru-Hole, Vertical, Heatsink Mounted; 3 In-Line Leads; Pitch 2.54 mm"
  rect 1.6x1.6 hole 1: 1(-2.54,0)
  round 1.6 hole 1: 2(0,0) 3(2.54,0)
  silkscreen extent -5.35,-1.85 5.35,2.85
XPort [mil] "Lantronix XPort"
  round 0 hole 128: 0(-350,-67) 0(-350,417)
  round 65 hole 35: 1(0,0) 2(-100,50) 3(0,100) 4(-100,150) 5(0,200) 6(-100,250) 7(0,300) 8(-100,350)
  round 100 hole 63: 9(119,491) 9(119,-141)
  silkscreen extent -777,-184 558,534

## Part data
C1 C2 C3 C4 C5 C6 C7 C8 C9 C10 C11 C12 C13 C14 C15 C16 C17 C18 C19 C22 C23 C24 C25 C26 C27 C28 C29 C30 C31 C32 C33 C34 C35 C36 C37 C38 C39 C40 C41 C42 C43 C44 C46 C47 C48 C52 C53 C54: "Ceramic Chip Capacitor - Standard"
C20 C21: library part C0402, "Ceramic Chip Capacitor - Standard"
C45 C49 C50 C51: "Polarized Capacitor (Axial)"
D1: library part Diode, "Default Diode"
D2: "Zener Diode"
D3 D4: library part BAS40DW-06
D5 D6: "Silicon AF Schottky Diode for High-Speed Switching"
F1 F2: library part "Fuseclip Mini vert"
JP11: "Header, 5-Pin, Dual row"
JP12 JP13: "Header, 2-Pin"
JP20: library part "HEADER 12F SHROUDED"
JP21: library part "HEADER 8F SHROUDED"
L1 L2 L3: library part Inductor, "Inductor"
L4: "Magnetic-Core Inductor"
Q1 Q2 Q3 Q4 Q5 Q6 Q7 Q8 Q14 Q16: "NPN General-purpose Transistor"
Q9 Q10 Q11 Q12: library part IRF7324, "HEXFET Power MOSFET"
Q13 Q15 Q17 Q19 Q21 Q22: "General Purpose Transistor PNP Silicon"
Q18 Q20 Q23 Q24 Q25 Q26 Q31 Q32 Q33 Q35: "General Purpose Transistor NPN Silicon"
Q27 Q28 Q29 Q30 Q36 Q37: "HEXFET Power MOSFET"
Q34: library part BSS84, "P-Channel Enhancement Mode Vertical DMOS FET"
R1 R3 R4 R5 R6 R9 R12 R13 R14 R15 R16 R21 R22 R25 R26 R29 R30 R33 R34 R35 R36 R37 R38 R39 R40 R43 R44 R46 R47 R48 R49 R50 R51 R52 R53 R54 R55 R56 R57 R58 R59 R60 R61 R62 R63 R64 R65 R66 R67 R68 R69 R70 R71 R72 R73 R76 R77 R80 R81 R84 R85 R88 R89 R90 R91 R92 R93 R94 R95 R96 R97 R98 R99 R100 R101 R102 R103: "Thick Film Chip Resistor, 1 Ohm to 10M Ohm Range, 5% Tolerance, 0805 Size, 0.125 W"
R2 R7 R8 R10 R11 R17 R18 R41 R42 R45: library part Res1, "Resistor"
R19 R20 R23 R24 R27 R28 R31 R32 R74 R75 R78 R79 R82 R83 R86 R87: library part "Resistor 5W ceramic"
U1 U2: library part MSP430F133, "Ultra Low Power 16 bit Mixed Signal uC"
U3: library part LM7131ACM5, "Tiny High-Speed Single-Supply Operational Amplifier"
U4: "Lithium Battery Protection Analog Front End"
U5 U6: "Tiny High-Speed Single-Supply Operational Amplifier"
U7: library part LTC1155CS8
U8: "3-to-8 Line Decoder"
U11: "Low-Cost, Ultra-Small, 3µA Single-Supply Comparator"
Y1 Y2: library part XTAL, "Crystal Oscillator"

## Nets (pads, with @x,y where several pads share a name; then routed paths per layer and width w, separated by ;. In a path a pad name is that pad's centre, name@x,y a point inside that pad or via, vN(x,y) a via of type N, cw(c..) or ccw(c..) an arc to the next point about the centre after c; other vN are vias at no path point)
+3DL: C1.2 C5.1 JP23.1 L1.1 Q14.1 Q16.1 R7.1 R100.2 R102.1 U1.1
+3DU: C2.2 C6.1 C16.2 C35.2 JP14.1 JP15.1 JP16.1 JP17.1 JP18.1 JP19.1 JP22.1 L2.1 R8.1 R42.2 R44.2 R51.1 R55.2 R98.1 U2.1 U6.5 U8.6 U8.16
+3H: C48.2 C49.1 C50.1 C51.1 L4.2 R101.2 U7.4 U9.2
+3L: C3.2 C7.1 C9.2 L1.2 R9.1 R10.1 R94.2 R95.2 U1.64 U3.18 U5.5
+3U: C4.2 C8.1 L2.2 Q35.1 R63.1 R64.1 U2.64 U4.18
/BATT_EN1: D3.1 JP21.4
/BATT_EN2: D3.2 JP20.5
/BATT_EN3: D3.4 JP20.6
/BATT_ON: JP13.2 U2.20
/COMMS_OFF: JP11.9 R102.2 U1.19
/ENETOFF: R100.1 U1.28 U7.5
/RST_ENET: R101.1 U1.29 U9.3
/TEMP_EN: R51.2 U2.44 U8.4
AGNDU: C2.1 C4.1 C6.2 C8.2 C12.2 C14.1 C16.1 C20.1 C21.2 C22.1 C23.2 C24.1 C30.1 C31.1 C32.1 C33.1 C34.1 C35.1 C39.1 JP9.5 JP14.4 JP15.4 JP16.4 JP17.4 JP18.4 JP19.4 JP22.7 Q5.2 Q10.1 Q13.1 Q15.1 Q18.1 Q20.1 R12.1 R30.2 R56.1 R62.2 R71.1 R75.2 R76.1 R80.1 R84.1 R103.2 RH1.2 U2.10 U2.11 U2.53 U2.62 U2.63 U3.1 U3.22 U4.8 U4.9 U4.12 U4.15 U6.2 U8.5 U8.8 U10.5 U10.10
BAT+: C41.2 D4.3 JP6.1 JP7.1 JP8.1 Q28.2 Q30.2
BAT-: C25.1 C26.1 C27.1 C28.1 C29.1 JP3.1 JP4.1 JP5.1 R16.1 R20.2 R104.4
CS0: JP14.5 R45.2
CS1: JP15.5 R46.2
CS2: JP16.5 R47.2
CS3: JP17.5 R48.2
CS4: JP18.5 R49.2
CS5: JP19.5 R50.2
CTS: U1.31 U9.8
F_RH: R54.2 R57.2 U2.42 U6.1
FUSE_EXT: C17.2 R58.1 R59.2 U1.61
FUSE_INT: C18.2 R60.1 R61.2 U1.60
NetC10_1: C10.1 R1.1 R3.2 U5.4
NetC22_2: C22.2 D4.1 R66.2 U4.22
NetC24_2: C24.2 D4.4 U4.1
NetC25_2: C25.2 R12.2 U3.3
NetC26_2: C26.2 R13.2 U3.4
NetC27_2: C27.2 R14.2 U3.5
NetC28_2: C28.2 R15.2 U3.6
NetC29_2: C29.2 R16.2 U3.7
NetC30_2: C30.2 R67.2 U4.3
NetC31_2: C31.2 R68.2 U4.4
NetC32_2: C32.2 R69.2 U4.5
NetC33_2: C33.2 R70.2 U4.6
NetC34_2: C34.2 R71.2 U4.7
NetC40_1: C40.1 D5.3 D6.1
NetC40_2: C40.2 U10.3
NetC44_2: C44.2 C45.1 L3.2 U7.7
NetC46_1: C46.1 U7.2
NetC47_1: C47.1 U7.1
NetC47_2: C47.2 D1.2 L4.1 U7.8
NetC52_2: C52.2 JP20.10
NetC53_2: C53.2 JP20.11
NetC54_2: C54.2 JP20.12
NetD3_3: D3.3 D3.6 Q31.2 R94.1
NetD3_5: D3.5 JP12.1 JP13.1
NetD4_2: D4.2 D4.5 Q34.2 R97.2
NetJP9_1: JP9.1 Q12.1 R67.1 R85.2
NetJP9_2: JP9.2 Q12.3 R68.1 R81.2 R87.2
NetJP9_3: JP9.3 Q11.1 R69.1 R77.2 R83.2
NetJP9_4: JP9.4 Q11.3 R70.1 R73.2 R79.2
NetJP9_6: JP9.6 Q10.3 R13.1 R26.2 R32.2
NetJP9_7: JP9.7 Q9.1 R14.1 R22.2 R28.2
NetJP9_8: JP9.8 Q9.3 R15.1 R18.2 R24.2
NetQ1_1: Q1.1 R17.2
NetQ1_3: Q1.3 Q9.4 R18.1
NetQ2_2: Q2.2 R21.2
NetQ2_3: Q2.3 Q9.2 R22.1
NetQ3_2: Q3.2 R25.2
NetQ3_3: Q3.3 Q10.4 R26.1
NetQ4_2: Q4.2 R29.2
NetQ4_3: Q4.3 Q10.2 R30.1
NetQ5_1: Q5.1 R72.2
NetQ5_3: Q5.3 Q11.4 R73.1
NetQ6_2: Q6.2 R76.2
NetQ6_3: Q6.3 Q11.2 R77.1
NetQ7_2: Q7.2 R80.2
NetQ7_3: Q7.3 Q12.4 R81.1
NetQ8_2: Q8.2 R84.2
NetQ8_3: Q8.3 Q12.2 R85.1
NetQ9_5: Q9.5 Q9.6 R19.1
NetQ9_7: Q9.7 Q9.8 R23.1
NetQ10_5: Q10.5 Q10.6 R27.1
NetQ10_7: Q10.7 Q10.8 R31.1
NetQ11_5: Q11.5 Q11.6 R74.1
NetQ11_7: Q11.7 Q11.8 R78.1
NetQ12_5: Q12.5 Q12.6 R82.1
NetQ12_7: Q12.7 Q12.8 R86.1
NetQ13_2: Q13.2 R40.1
NetQ14_2: Q14.2 R43.1
NetQ15_2: Q15.2 R38.1
NetQ16_2: Q16.2 R41.1
NetQ17_1: Q17.1 U3.20
NetQ17_2: Q17.2 R35.1
NetQ18_2: Q18.2 R35.2
NetQ18_3: Q18.3 Q21.3
NetQ19_1: Q19.1 U3.2
NetQ19_2: Q19.2 R33.1
NetQ20_2: Q20.2 R33.2
NetQ20_3: Q20.3 Q22.3
NetQ21_1: Q21.1 U4.20
NetQ21_2: Q21.2 R36.1
NetQ22_1: Q22.1 U4.2
NetQ22_2: Q22.2 R34.1
NetQ23_1: Q23.1 Q24.1 Q25.2 Q26.2 Q27.3 Q28.3 Q29.3 Q30.3
NetQ23_2: Q23.2 R36.2
NetQ23_3: Q23.3 Q25.1 R90.1
NetQ24_2: Q24.2 R34.2
NetQ24_3: Q24.3 Q26.1 R91.1
NetQ25_3: Q25.3 Q27.1 Q29.1 R88.1
NetQ26_3: Q26.3 Q28.1 Q30.1 R89.1
NetQ31_1: Q31.1 Q32.1 Q32.3 R95.1
NetQ31_3: Q31.3 R96.1
NetQ32_2: Q32.2 Q33.1 Q33.3
NetQ34_3: Q34.3 R96.2 R97.1
NetQ35_2: Q35.2 R62.1
NetQ35_3: Q35.3 R93.2 U11.4
NetQ36_1: Q36.1 Q37.1 U11.1
NetR1_2: R1.2 R104.3 U3.8
NetR2_1: R2.1 R4.2 R5.1 U5.3
NetR2_2: R2.2 R104.2 U3.9
NetR11_1: R11.1 U3.11
NetR19_2: R19.2 R20.1
NetR23_2: R23.2 R24.1
NetR27_2: R27.2 R28.1
NetR31_2: R31.2 R32.1
NetR45_1: R45.1 U8.15
NetR46_1: R46.1 U8.14
NetR47_1: R47.1 U8.13
NetR48_1: R48.1 U8.12
NetR49_1: R49.1 U8.11
NetR50_1: R50.1 U8.10
NetR52_1: R52.1 U2.47
NetR53_1: R53.1 U2.45
NetR54_1: R54.1 RH1.1 U6.4
NetR55_1: R55.1 R56.2 R57.1 U6.3
NetR65_1: R65.1 U4.11
NetR66_1: R66.1 U4.23
NetR74_2: R74.2 R75.1
NetR78_2: R78.2 R79.1
NetR82_2: R82.2 R83.1
NetR86_2: R86.2 R87.1
NetR92_2: R92.2 U11.3
NetR103_1: R103.1 U3.23
NetU1_8: U1.8 Y1.2
NetU1_9: U1.9 Y1.1
NetU2_8: U2.8 Y2.2
NetU2_9: U2.9 Y2.1
NetU2_49: U2.49 U8.1
NetU2_50: U2.50 U8.2
NetU2_51: U2.51 U8.3
PWR+: F1.1 F2.1 JP2.1 JP11.1 JP11.3 JP11.5 JP11.7 JP21.1 JP21.2 JP21.3 Q36.3 Q37.3 R58.2
PWR-: C1.1 C3.1 C5.2 C7.2 C9.1 C11.2 C13.2 C15.1 C17.1 C18.1 C19.1 C21.1 C23.1 C36.1 C37.1 C38.1 C43.1 C44.1 C45.2 C46.2 C48.1 C49.2 C50.2 C51.2 C52.1 C53.1 C54.1 D1.1 D2.1 JP1.1 JP10.3 JP11.2 JP11.4 JP11.6 JP11.8 JP11.10 JP12.2 JP20.3 JP20.4 JP20.8 JP20.9 JP21.5 JP21.6 JP21.7 JP21.8 JP23.7 Q1.2 Q17.3 Q19.3 Q33.2 R5.2 R21.1 R25.1 R29.1 R37.1 R39.1 R59.1 R61.1 R99.1 R104.1 U1.10 U1.11 U1.53 U1.62 U1.63 U3.12 U3.15 U5.2 U7.3 U7.6 U9.1 U9.9
PWRF+: C36.2 C37.2 C38.2 C42.1 D2.2 D4.6 F1.2 F2.2 Q27.2 Q29.2 R60.2 R92.1 U11.2
PWRISO+: JP20.1 JP20.2 JP20.7 Q36.2 Q37.2 R93.1
RSTL: JP23.2 R7.2 U1.58
RSTU: JP22.2 R8.2 U2.58
RTS: U1.30 U9.6
RX0L: U1.33 U9.4
RX0U: Q14.3 R44.1 U2.33
RX1L: Q13.3 R39.2 U1.35
RX1U: Q16.3 R42.1 U2.35
RX3V: JP10.2 R41.2
SC_T: JP14.3 JP15.3 JP16.3 JP17.3 JP18.3 JP19.3 R52.2
SCLKL: R10.2 U1.14 U3.13
SCLKU: R64.2 U2.14 U4.13
SDATL: R9.2 U1.13 U3.14
SDATU: R63.2 U2.13 U4.14
SI/O_T: JP14.2 JP15.2 JP16.2 JP17.2 JP18.2 JP19.2 R53.2 U2.46
SLPL: U1.15 U3.19
SLPU: U2.15 U4.19
TB0L: Q4.1 U1.36
TB0U: Q8.1 U2.36
TB1L: Q3.1 U1.37
TB1U: Q7.1 U2.37
TB2L: Q2.1 U1.38
TB2U: Q6.1 U2.38
TB3L: R17.1 U1.39
TB3U: R72.1 U2.39
TCKL: JP23.3 U1.57
TCKU: JP22.3 U2.57
TDIL: JP23.6 U1.55
TDIU: JP22.6 U2.55
TDOL: JP23.5 U1.54
TDOU: JP22.5 U2.54
TMSL: JP23.4 U1.56
TMSU: JP22.4 U2.56
TX0L: U1.32 U9.5
TX0U: R40.2 U2.32
TX1L: R43.2 U1.34
TX1U: R38.2 U2.34
TX3V: JP10.1 Q15.3 R37.2
UP/LOW_L: R99.2 U1.27
UP/LOW_U: R98.2 U2.27
V_CURRENT_FAST: C10.2 R3.1 R6.2 U1.6 U5.1
V_CURRENT_SLOW: C11.1 R6.1 U1.5
V_GATE: C41.1 C42.2 D6.3 R88.2 R89.2 R90.2 R91.2 U11.5
V_ON: C39.2 C43.2 D5.1 L3.1 Q34.1 U10.16
VCELL-L: C19.2 R11.2 U1.59
VCELL-U: C20.2 R65.2 U2.59
VREF_L: C13.1 C15.2 R4.1 U1.7
VREF_U: C12.1 C14.2 U2.7
WDIL: U1.43 U3.10
WDIU: U2.43 U4.10
XAL: U1.12 U3.16
XAU: U2.12 U4.16
pads on no net: D5.2 D6.2 Designator160.0 Designator161.0 Designator162.0 Designator163.0 Designator164.0 Designator165.0 JP9.0 JP10.0 JP20.0 JP21.0 JP22.0 JP22.8 JP23.0 JP23.8 U1.2 U1.3 U1.4 U1.16 U1.17 U1.18 U1.20 U1.21 U1.22 U1.23 U1.24 U1.25 U1.26 U1.40 U1.41 U1.42 U1.44 U1.45 U1.46 U1.47 U1.48 U1.49 U1.50 U1.51 U1.52 U2.2 U2.3 U2.4 U2.5 U2.6 U2.16 U2.17 U2.18 U2.19 U2.21 U2.22 U2.23 U2.24 U2.25 U2.26 U2.28 U2.29 U2.30 U2.31 U2.40 U2.41 U2.48 U2.52 U2.60 U2.61 U3.17 U3.21 U3.24 U4.17 U4.21 U4.24 U8.7 U8.9 U9.0 U9.7 U10.1 U10.2 U10.4 U10.6 U10.7 U10.8 U10.9 U10.11 U10.12 U10.13 U10.14 U10.15

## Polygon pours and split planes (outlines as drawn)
PWRISO+ on Top Layer (hatched 45Degree grid 20 track 25): 9584.53,4815 9962.75,4596.63 10212.75,5029.65 10069.24,5531.08 9744.48,5718.58 9313.23,4971.63
PWR- on Top Layer (hatched 45Degree grid 20 track 25): 10183.86,5854.62 10357.07,5754.62 10613.29,4798.4 10363.29,4365.38 10006.05,4571.63 10262.3,5015.47 10081.37,5677.09 10183.86,5854.62
PWR+ on Top Layer (hatched 45Degree grid 20 track 25): 8342.77,3474.26 8939.13,2441.32 9437.1,2728.82 8840.73,3761.76 8342.77,3474.26
PWR- on Top Layer (hatched 45Degree grid 20 track 25): 9382,4074.26 9978.37,3041.32 9480.4,2753.82 8884.03,3786.76 9382,4074.26
BAT- on Top Layer (hatched 45Degree grid 20 track 25, remove dead copper): 7650,5800 8200,6350 8400,6350 8650,6100 8750,6100 8800,6050 8800,5900 8800,5750 8750,5700 8650,5600 8150,5600 8050,5500 8000,5450 7900,5450 7650,5700
PWRISO+ on Bottom Layer (hatched 45Degree grid 20 track 25): 10212.5,5450 10212.5,5025 9737.5,4550 8250,4550 8250,5500 8800,5500 9000,5700 9762.5,5700
PWR+ on Bottom Layer (hatched 45Degree grid 20 track 25): 8925,3937.5 8925,3612.5 9187.5,3175 9075,3062.5 8000,3062.5 7925,3137.5 7925,4437.5 8000,4512.5 8900,4512.5 9137.5,4050 8925,3918.68
PWR- on Bottom Layer (hatched 45Degree grid 20 track 25, remove dead copper): 10250,5475 9900,5675 9900,6000 9800,6100 9800,6400 9925,6525 10375,6525 10500,6400 10900,6000 10900,5487.5 10637.5,5075 10637.5,4762.5 10637.5,4612.5 10637.5,4062.5 10637.5,3850 10637.5,3675 10025,3062.5 9487.5,2750 8950.45,3633.01 8950,3912.5 9225,4075 9912.5,4762.5 10250,5012.5
BAT- on Bottom Layer (hatched 45Degree grid 20 track 25, remove dead copper): 7650,5800 8200,6350 8400,6350 8650,6100 8750,6100 8800,6050 8800,5900 8800,5750 8750,5700 8650,5600 8150,5600 8050,5500 8000,5450 7900,5450 7650,5700
NetQ23_1 on Bottom Layer (hatched 45Degree grid 20 track 25): 7500,4100 7425,4025 6875,4025 6450,4450 6450,4950 6575,5075 7400,5075 7500,4975
PWRF+ on Bottom Layer (hatched 45Degree grid 20 track 25): 7462.5,4012.5 7537.5,4087.5 7537.5,4225 7612.5,4300 7825,4300 7900,4225 7900,3725 7675,3500 6675,3500 6600,3575 6600,3925 6675,4000 7450,4000
BAT+ on Bottom Layer (hatched 45Degree grid 20 track 25): 5750,6350 5600,6350 5350,6100 5350,5800 6050,5100 7225,5100 7300,5175 7300,5650 6450,5650

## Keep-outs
Keep-Out Layer:
  circle w50: c7000,7000 r1325
  circle w100: c8139.39,8973.48 r125
  circle w100: c5860.61,5026.52 r125
  circle w125: c11298.37,8151.74 r125
  circle w125: c10146.63,10146.63 r125
  circle w125: c8151.74,11298.37 r125
  circle w125: c5848.26,11298.37 r125
  circle w125: c3853.37,10146.63 r125
  circle w125: c2701.63,8151.74 r125
  circle w125: c2701.63,5848.26 r125
  circle w125: c3853.37,3853.37 r125
  circle w125: c5848.26,2701.63 r125
  circle w125: c8151.74,2701.63 r125
  circle w125: c10146.63,3853.37 r125
  circle w125: c11298.37,5848.26 r125

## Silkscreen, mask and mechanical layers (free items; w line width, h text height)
Top Overlay:
  text "TAPE" at 6550,5475 h60
  text "TAPE" at 7237.5,5475 h60
  text "TAPE" at 8350,5375 h60
  text "TAPE" at 9025,5375 h60
  text "TAPE" at 6775,4775 h60 r180
  text "TAPE" at 7462.5,4775 h60 r180
  text "TAPE" at 8575,4675 h60 r180
  text "TAPE" at 9250,4675 h60 r180
  text "TAPE" at 6550,4325 h60
  text "TAPE" at 7237.5,4325 h60
  text "TAPE" at 6775,3625 h60 r180
  text "TAPE" at 7462.5,3625 h60 r180
Board Outline:
  circle w10: c7000,7000 r1350
  lines w10: 1794.91,6314.74 2149.63,4990.91 2834.9,3804 3804,2834.9 4990.91,2149.63 6314.74,1794.92 7685.26,1794.91 9009.09,2149.63 10196,2834.9 11165.1,3804 11850.37,4990.91 12205.08,6314.74 12205.08,7685.26 11850.37,9009.09 11165.1,10196 10196,11165.1 9009.09,11850.37 7685.26,12205.08 6314.74,12205.08 4990.91,11850.37 3804,11165.1 2834.9,10196 2149.63,9009.09 1794.92,7685.26 1794.91,6314.74
Mech Reference:
  drawing of 354 lines, arcs and shapes, not listed
  text "MBARI Comms" at 3487.5,9287.5 h60
Mechanical Cells:
  circle w10: c12382.82,6291.34 r708.66
  circle w10: c12382.82,7708.66 r708.66
  circle w10: c11155.4,7000 r708.66
  circle w10: c9985.39,7799.93 r708.66
  circle w10: c8572.16,7907.69 r708.66
  circle w10: c8572.16,6092.31 r708.66
  circle w10: c9985.39,6200.07 r708.66
  circle w10: c9185.45,4814.55 r708.66
  circle w10: c10598.68,4922.3 r708.66
  circle w10: c12015.99,4922.31 r708.66
  circle w10: c11307.33,3694.87 r708.66
  circle w10: c9077.7,3401.32 r708.66
  circle w10: c7799.93,4014.61 r708.66
  circle w10: c7000,5184.62 r708.66
  circle w10: c9077.69,1984.01 r708.66
  circle w10: c10305.13,2692.67 r708.66
  circle w10: c7708.66,1617.18 r708.66
  circle w10: c6200.07,4014.61 r708.66
  circle w10: c6291.34,1617.18 r708.66
  circle w10: c4922.31,1984.01 r708.66
  circle w10: c4922.3,3401.32 r708.66
  circle w10: c4814.55,4814.55 r708.66
  circle w10: c5427.84,6092.31 r708.66
  circle w10: c3694.87,2692.67 r708.66
  circle w10: c2692.67,3694.87 r708.66
  circle w10: c3401.32,4922.3 r708.66
  circle w10: c1984.01,4922.31 r708.66
  circle w10: c4014.61,6200.07 r708.66
  circle w10: c2844.6,7000 r708.66
  circle w10: c1617.18,6291.34 r708.66
  circle w10: c1617.18,7708.66 r708.66
  circle w10: c4014.61,7799.68 r708.66
  circle w10: c5427.84,7907.69 r708.66
  circle w10: c4814.55,9185.45 r708.66
  circle w10: c3401.32,9077.7 r708.66
  circle w10: c1984.01,9077.69 r708.66
  circle w10: c2692.67,10305.13 r708.66
  circle w10: c4922.3,10598.68 r708.66
  circle w10: c6200.07,9985.39 r708.66
  circle w10: c7000,8815.38 r708.66
  circle w10: c7799.93,9985.39 r708.66
  circle w10: c9185.45,9185.45 r708.66
  circle w10: c10598.68,9077.7 r708.66
  circle w10: c12015.99,9077.69 r708.66
  circle w10: c11307.33,10305.13 r708.66
  circle w10: c9077.7,10598.68 r708.66
  circle w10: c10305.13,11307.33 r708.66
  circle w10: c9077.69,12015.99 r708.66
  circle w10: c7000,11155.4 r708.66
  circle w10: c7708.66,12382.82 r708.66
  circle w10: c6291.34,12382.82 r708.66
  circle w10: c4922.31,12015.99 r708.66
  circle w10: c3694.87,11307.33 r708.66
  circle w10: c7000,2844.6 r708.66
  lines w10: 1051,6217 1051,7783 ; 1051.05,6216.61 1456.36,4703.97 ; 1051.05,7783.39 1456.36,9296.03 ; 1456.51,4703.6 2239.51,3347.4 ; 1456.51,9296.4 2239.51,10652.6 ; 2239.76,3347.09 3347.09,2239.76 ; 2239.76,10652.91 3347.09,11760.24 ; 3347.4,2239.51 4703.6,1456.51 ; 3347.4,11760.49 4703.6,12543.49 ; 4703.97,1456.36 6216.61,1051.05 ; 4703.97,12543.64 6216.61,12948.95 ; 6217,1051 7783,1051 ; 6217,12949 7783,12949 ; 6349.14,8182.74 cw(c6469.67,7963.72) 6717.53,7996.35 ; 6717.49,7996.65 ccw(c6866.21,8016.23) 6885.79,7867.51 ; 6866.21,7866.23 7133.79,7866.23 ; 7114.21,7867.51 ccw(c7133.79,8016.23) 7282.51,7996.65 ; 7282.47,7996.35 cw(c7530.33,7963.72) 7650.86,8182.74 ; 7783.39,1051.05 9296.03,1456.36 ; 7783.39,12948.95 9296.03,12543.64 ; 9296.4,1456.51 10652.6,2239.51 ; 9296.4,12543.49 10652.6,11760.49 ; 10652.91,2239.76 11760.24,3347.09 ; 10652.91,11760.24 11760.24,10652.91 ; 11760.49,3347.4 12543.49,4703.6 ; 11760.49,10652.6 12543.49,9296.4 ; 12543.64,4703.97 12948.95,6216.61 ; 12543.64,9296.03 12948.95,7783.39 ; 12949,6217 12949,7783 ; 5700,6775 5850,6700 5850,7300 5700,7225 5700,6775 ; 5759.16,6517.91 ccw(c7000,7000) 5962.08,6166.44 cw(c6092.31,5427.84) 6797.08,5684.35 ccw(c7000,7000) 7202.92,5684.35 cw(c7907.69,5427.84) 8037.92,6166.44 ccw(c7000,7000) 8240.84,6517.91 cw(c8815.38,7000) 8240.84,7482.09 ccw(c7000,7000) 8037.92,7833.56 cw(c7907.69,8572.16) 7399.07,8020.98 7329.53,7843.45 cw(c7232.94,7869.33) 7207.06,7772.74 ccw(c7000,7000) 6434.31,7565.69 cw(c6363.6,7636.4) 6292.89,7565.69 5960.36,7831.42 ccw(c7000,7000) 5759.16,7482.09 cw(c5184.62,7000) 5759.16,6517.91 ; 8150,6700 8150,7300 8300,7225 8300,6775 8150,6700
